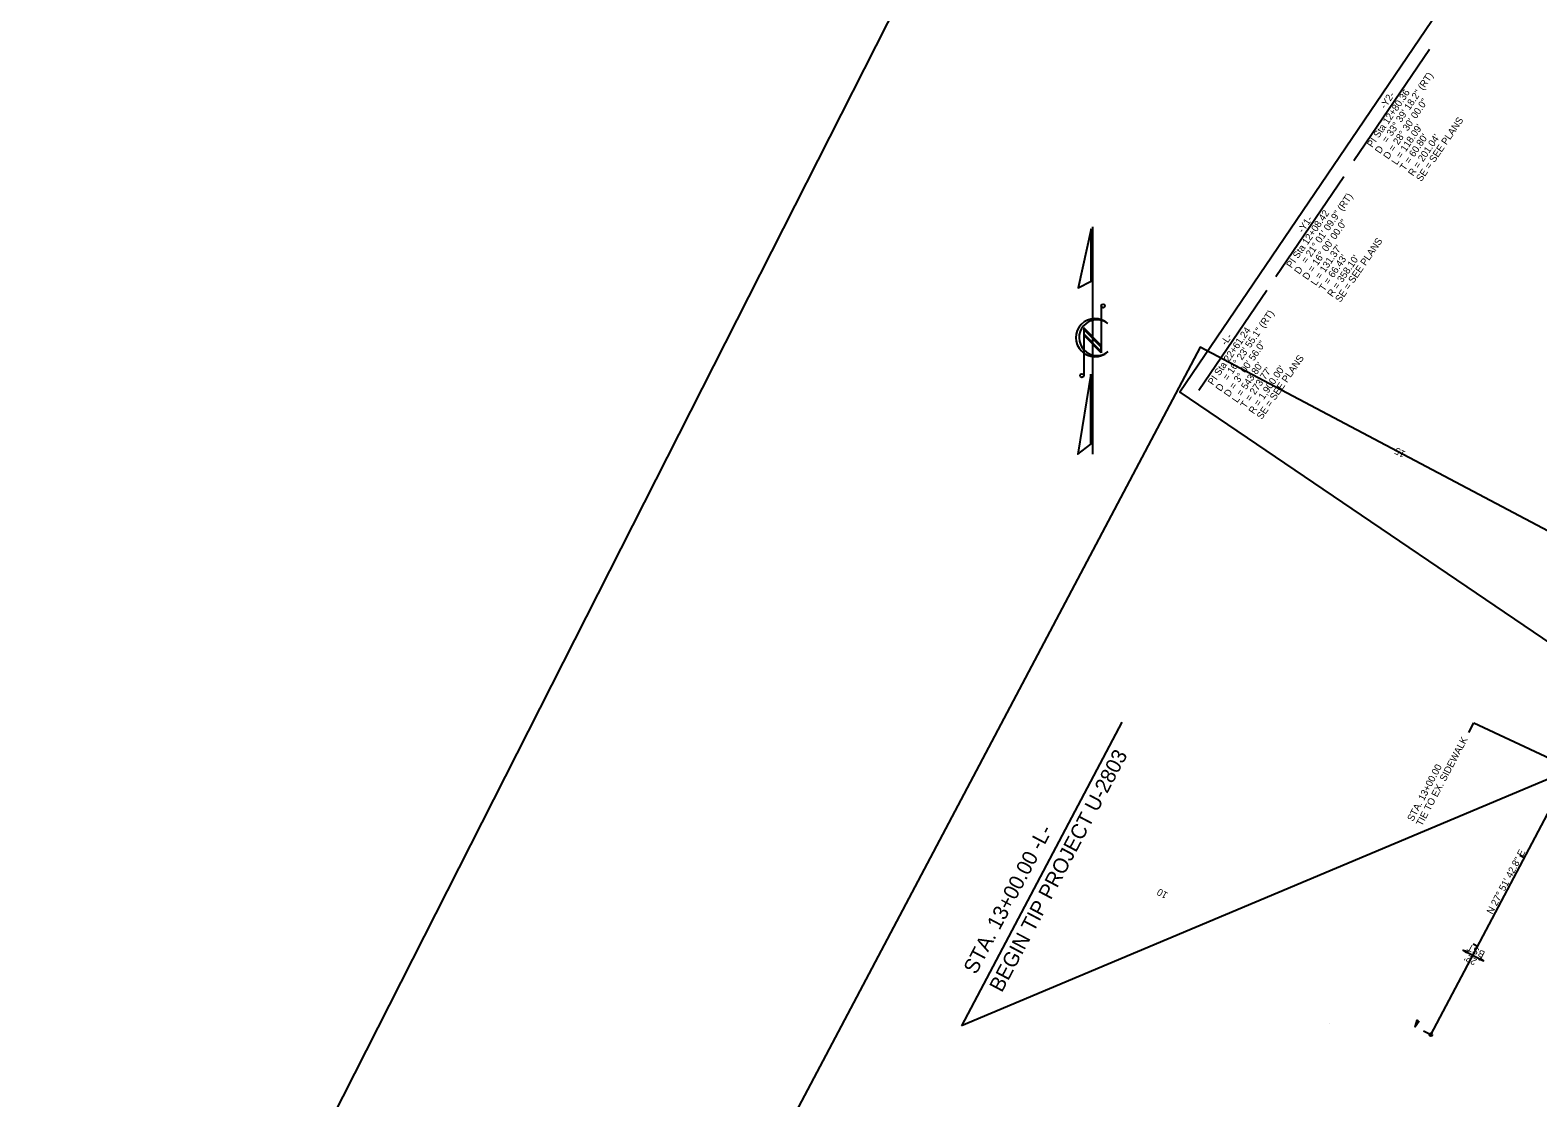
# Model space of a CAD drawing. Extents: x 1974386 to 1979988, y 776712 to 784860.
# Drawn here: x 1974386 to 1975893, y 778330 to 779397 of the extents above; entities that cross this region are included whole.
import ezdxf

# ---------------------------------------------------------------- set-up
doc = ezdxf.new("R2010")
doc.units = 0
for name, color, linetype in [('Default', 7, 'Continuous'), ('Old_Level_11', 7, 'Continuous'), ('Prop Dimension', 7, 'Continuous'), ('Prop Dimension Text', 7, 'Continuous'), ('Prop DSN Text', 7, 'Continuous'), ('Prop Horizontal Alignment', 7, 'Continuous'), ('Prop Horizontal Alignment Curve and Spiral Data', 7, 'Continuous'), ('Prop Horizontal Alignment Direction Label', 7, 'Continuous'), ('Prop Horizontal Alignment Station Label', 7, 'Continuous'), ('Prop Horizontal Alignment Tick Label', 7, 'Continuous'), ('Prop Horizontal Alignment Tick Large', 7, 'Continuous'), ('Prop Horizontal Alignment Tick Small', 7, 'Continuous'), ('Prop Lane Arrow CELL', 7, 'Continuous'), ('Prop Terminator CELL', 7, 'Continuous'), ('Sheet Layout Plan Border', 7, 'Continuous'), ('Sheet North Arrow CELL', 7, 'Continuous')]:
    doc.layers.add(name, color=color, linetype=linetype)

msp = doc.modelspace()

# ---------------------------------------------------------------- linework, layer by layer
at = {"layer": 'Default'}
msp.add_lwpolyline([(1978010, 784859.9), (1974385.9, 777715.1), (1976364, 776711.7), (1979988.1, 783856.5)], close=True, dxfattribs=at)
at = {"layer": 'Old_Level_11'}
for p in [(1975477, 778705.4), (1975925.9, 778658.1)]:
    msp.add_line(p, (1975316.6, 778402), dxfattribs=at)
at = {"layer": 'Prop Dimension'}
msp.add_line((1975818.2, 778477.5), (1975838.4, 778466.8), dxfattribs=at)
at = {"layer": 'Prop DSN Text'}
for p, q in [((1975823.8, 778695.2), (1975828.7, 778704.6)), ((1975828.7, 778704.6), (1975905.1, 778669.1))]:
    msp.add_line(p, q, dxfattribs=at)
at = {"layer": 'Prop Horizontal Alignment'}
msp.add_line((1975785.7, 778392.9), (1976247.2, 779265.9), dxfattribs=at)
at = {"layer": 'Prop Horizontal Alignment Station Label'}
for p, q in [((1975708.9, 779266.9), (1975784.3, 779378.1)), ((1975630.8, 779150.8), (1975698.7, 779250.8)), ((1975553.9, 779037.3), (1975621.7, 779137.3))]:
    msp.add_line(p, q, dxfattribs=at)
msp.add_circle((1975785.7, 778392.9), 1.5, dxfattribs=at)
at = {"layer": 'Prop Horizontal Alignment Tick Large'}
msp.add_line((1975785.7, 778392.9), (1975778.6, 778396.6), dxfattribs=at)
at = {"layer": 'Prop Horizontal Alignment Tick Small'}
for p, q in [((1975879.2, 778569.7), (1975874.8, 778572)), ((1975832.4, 778481.3), (1975828, 778483.6))]:
    msp.add_line(p, q, dxfattribs=at)
at = {"layer": 'Prop Lane Arrow CELL'}
msp.add_line((1975684.5, 778404.3), (1975684.5, 778404.3), dxfattribs=at)
at = {"layer": 'Prop Terminator CELL'}
for points in [[(1975821.9, 778474.7), (1975818.2, 778477.5), (1975822.6, 778476.1), (1975821.7, 778475.6)], [(1975834.8, 778469.6), (1975838.4, 778466.8), (1975834.1, 778468.2), (1975834.9, 778468.6)], [(1975774.1, 778406.5), (1975770, 778401), (1975772, 778407.6), (1975772.7, 778406.3)]]:
    msp.add_lwpolyline(points, close=True, dxfattribs=at)
at = {"layer": 'Sheet Layout Plan Border'}
for points in [[(1976403.9, 778445.7), (1977189.9, 779604.2), (1976321, 780193.7), (1975535, 779035.2)], [(1974902.4, 777845.2), (1975830.6, 777354.5), (1975830.6, 777354.5), (1976483.5, 778589.6), (1976483.5, 778589.6), (1975555.2, 779080.3), (1975555.2, 779080.3)]]:
    msp.add_lwpolyline(points, close=True, dxfattribs=at)
at = {"layer": 'Sheet North Arrow CELL'}
for p, q in [((1975447.8, 778973.1), (1975447.8, 779200.6)), ((1975456.4, 779121.4), (1975456.4, 779074.7)), ((1975456.4, 779082), (1975439, 779099.4)), ((1975439, 779099.4), (1975439, 779051.9)), ((1975456.4, 779080.3), (1975439, 779097.7)), ((1975439, 779097.7), (1975439, 779093.4)), ((1975462.8, 779104), (1975463.1, 779103.8)), ((1975456.4, 779076), (1975439, 779093.4)), ((1975439, 779093.4), (1975456.4, 779076)), ((1975456.4, 779074.7), (1975439, 779092.1)), ((1975456.4, 779076), (1975456.4, 779080.3))]:
    msp.add_line(p, q, dxfattribs=at)
for points in [[(1975446.2, 779198.6), (1975433.2, 779139.5), (1975446.2, 779146.1)], [(1975445.9, 779053.2), (1975433.1, 778973.1), (1975445.9, 778983.2)]]:
    msp.add_lwpolyline(points, close=True, dxfattribs=at)
for centre in [(1975458.2, 779121.4), (1975437.1, 779051.8)]:
    msp.add_circle(centre, 1.85, dxfattribs=at)
for centre, radius, start, end in [((1975450.2, 779089.7), 19.1, 47.84, 312.3941), ((1975452.1, 779089.7), 17.9, 53.095, 308.6287)]:
    msp.add_arc(centre, radius, start, end, dxfattribs=at)

# ---------------------------------------------------------------- texts
at = {"layer": 'Old_Level_11'}
for s, p in [('BEGIN TIP PROJECT U-2803', (1975357, 778434.4)), ('STA. 13+00.00 -L-', (1975331.2, 778452.4))]:
    msp.add_text(s, height=15, rotation=62.1381, dxfattribs=at).set_placement(p)
at = {"layer": 'Prop Dimension Text'}
for s, p in [('BST', (1975840.6, 778475.5)), ("22'", (1975832.4, 778468.2))]:
    msp.add_text(s, height=7, rotation=152.2175, dxfattribs=at).set_placement(p)
at = {"layer": 'Prop DSN Text'}
for s, p in [('TIE TO EX. SIDEWALK', (1975776.8, 778600.9)), ('STA. 13+00.00', (1975767.9, 778605.6))]:
    msp.add_text(s, height=7, rotation=62.2664, dxfattribs=at).set_placement(p)
at = {"layer": 'Prop Horizontal Alignment Curve and Spiral Data'}
for s, rotation, p in [('= 33%%d 39\' 18.2" (RT)', 55.761, (1975742.1, 779283.8)), ('PI Sta 12+80.36', 55.761, (1975727.2, 779279.2)), ('-Y2-', 55.761, (1975740.1, 779317.8)), ('D = 28%%d 30\' 00.0"', 55.761, (1975743.4, 779267.4)), ('SE = SEE PLANS', 55.5675, (1975776.2, 779245.1)), ("L = 118.09'", 55.761, (1975751.7, 779261.8)), ("T = 60.80'", 55.761, (1975759.9, 779256.1)), ("R = 201.04'", 55.761, (1975768.2, 779250.5)), ('D', 55.761, (1975735.1, 779273)), ('= 21%%d 01\' 09.9" (RT)', 55.5333, (1975661.4, 779163.2)), ('PI Sta 12+08.42', 55.5333, (1975646.5, 779158.7)), ('-Y1-', 55.5333, (1975657.9, 779193.8)), ('D = 16%%d 00\' 00.0"', 55.5333, (1975662.6, 779146.8)), ('SE = SEE PLANS', 55.5675, (1975695.3, 779124.4)), ("L = 131.37'", 55.5333, (1975670.9, 779141.2)), ("T = 66.43'", 55.5333, (1975679.1, 779135.5)), ("R = 358.10'", 55.5333, (1975687.4, 779129.8)), ('D', 55.5333, (1975654.4, 779152.5)), ('= 16%%d 23\' 55.1" (RT)', 55.5675, (1975582.9, 779046.2)), ('PI Sta 22+61.24', 55.5675, (1975568, 779041.6)), ('-L-', 55.5333, (1975581, 779081.4)), ('D = 3%%d 00\' 56.0"', 55.5675, (1975584.1, 779029.8)), ('SE = SEE PLANS', 55.5675, (1975616.8, 779007.4)), ("L = 543.80'", 55.5675, (1975592.3, 779024.1)), ("T = 273.77'", 55.5675, (1975600.6, 779018.5)), ("R = 1,900.00'", 55.5675, (1975608.8, 779012.8)), ('D', 55.5675, (1975575.8, 779035.4))]:
    msp.add_text(s, height=7, rotation=rotation, dxfattribs=at).set_placement(p)
at = {"layer": 'Prop Horizontal Alignment Direction Label'}
msp.add_text('N 27%%d 51\' 42.8" E', height=7, rotation=62.1381, dxfattribs=at).set_placement((1975847.2, 778512.8))
at = {"layer": 'Prop Horizontal Alignment Tick Label'}
for s, rotation, p in [('15', 152.1381, (1975761, 778975.5)), ('10', 150.9082, (1975523.6, 778534.4))]:
    msp.add_text(s, height=7, rotation=rotation, dxfattribs=at).set_placement(p)

doc.saveas('drawing.dxf')
